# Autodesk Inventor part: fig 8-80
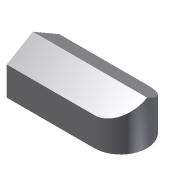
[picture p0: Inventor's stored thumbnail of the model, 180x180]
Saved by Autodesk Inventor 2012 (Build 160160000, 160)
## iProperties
Created: 2011-07
Part Number: fig 8-80
Material: Default
Document SubType Name: Modeling
Designer: CadCim
Density: 1 g/cm^3
Author: CadCim
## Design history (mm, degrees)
sketch "Sketch1"
  geometry: L1 (-16, 5)-(-16, -7); L2 (-16, -7)-(4, -7); L3 (4, 5)-(-16, 5); A1 r 6 centre (4, -1) between (4, -7) and (4, 5); 1 further point
  constraints: 6 end point, 2 point on circle, 2 tangent, 1 centre point, 1 parallel, 1 perpendicular, 1 vertical
extrude "Extrusion1" new body sketch "Sketch1" distance "d0" = 10; taper "d1" = 0 deg
sketch "Sketch2"
  geometry: L1 (-16, -1)-(10, -1); 1 further point
  constraints: 2 end point, 1 horizontal
feature "FaceDraft1" sketch "Sketch2" dims angle "d2" = 30 deg
body "Solid1"
